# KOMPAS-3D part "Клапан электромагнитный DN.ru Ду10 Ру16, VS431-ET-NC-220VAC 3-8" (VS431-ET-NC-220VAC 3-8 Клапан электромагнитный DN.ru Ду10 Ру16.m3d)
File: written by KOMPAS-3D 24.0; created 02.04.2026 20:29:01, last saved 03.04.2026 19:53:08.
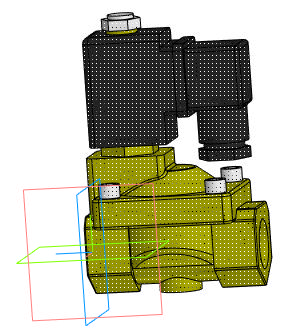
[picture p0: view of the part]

Document properties: Автор: artio; Полное имя файла: C:\Users\artio\OneDrive\Рабочий стол\Клапан электромагнитный DN.ru\VS431\VS431-ET-NC\VS431-ET-NC-220VAC\Ду10\VS431-ET-NC-220VAC 3-8 Клапан электромагнитный DN.ru Ду10 Ру16.m3d

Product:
- Body: Тело 1  | qty 1
    Масса: 1.030062
- Part/product: Клапан электромагнитный DN.ru Ду10 Ру16  | designation VS431-ET-NC-220VAC 3-8
    Масса: 0.62
    Раздел спецификации: Прочие изделия
    Примечание: D130-04704
    additional columns: ef56311e-7521-43dc-8291-0e6108b3d81d; VS400-ET-NC-220VAC 3-8; artio; c; Шероховатость не задана; Да

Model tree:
1. Операция без истории:1

Expressions: VS431-ET-NC-220VAC 3-8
